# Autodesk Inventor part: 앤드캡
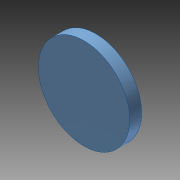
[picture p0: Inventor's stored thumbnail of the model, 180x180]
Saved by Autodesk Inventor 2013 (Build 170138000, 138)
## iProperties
Created: 2023-03
Part Number: 앤드캡
Material: 알루미늄 6061
Document SubType Name: Modeling
Designer: mdu-01
Density: 1 g/cm^3
Author: mdu-01
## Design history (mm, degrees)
node "작업 평면1"
sketch "스케치1"
  geometry: C1 r 23 at (0, 0); A1 r 24 centre (0, 0) between (-23.427, 5.212) and (-7.2, -22.895) reference; 1 further point
  constraints: 1 centre point, 1 coincident
  dimensions: "d2" = 1 radial gap between concentric circles of A1 C1
extrude "돌출1" new body sketch "스케치1" stored distance "d0" = 10; taper "d1" = 0 deg
sketch "스케치2"
  geometry: C1 r 1.23 at (0, -17) reference; 1 further point
hole "구멍1" sketch "스케치2" at (0, -17) diameter "d3" = 3.4; stored, may be unused: countersink angle "d7" = 90 deg, drill point angle "d9" = 118 deg; dims "d4" = 6, "d5" = 6.5, "d6" = 3.4, "d8" = 8
chamfer "모따기1" distance "d13" = 1; stored, may be unused: second distance "d14" = 2, angle "d15" = 45 deg
node "솔리드1"
pattern_circular "원형 패턴1" dims angle "d11" = 360 deg
node "참조1"
node "참조2"
